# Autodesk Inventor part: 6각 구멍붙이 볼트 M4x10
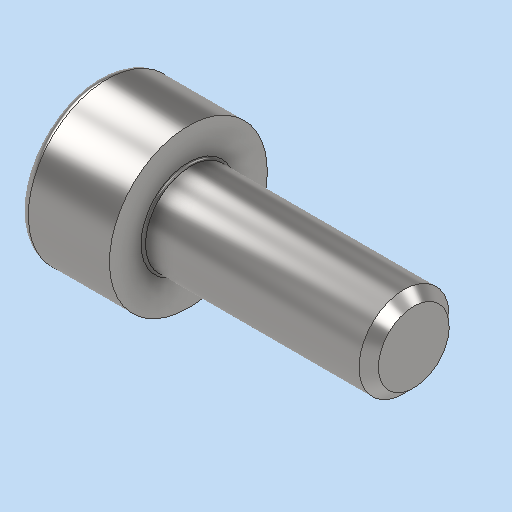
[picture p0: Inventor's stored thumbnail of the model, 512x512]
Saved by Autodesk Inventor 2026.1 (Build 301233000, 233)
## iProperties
Created: 2025-11
Part Number: 6각 구멍붙이 볼트 M4x10
Material: 강철, 연강
Description: 6각머리 태핑 나사
Document SubType Name: Modeling
Designer: PC-30
Density: 7.85 g/cm^3
Appearance: 기본값
Author: jhkim
Sending System: Autodesk Inventor 2026
Preprocessor: ST-DEVELOPER v20.1
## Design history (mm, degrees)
feature "Solid1"
node "솔리드1"
